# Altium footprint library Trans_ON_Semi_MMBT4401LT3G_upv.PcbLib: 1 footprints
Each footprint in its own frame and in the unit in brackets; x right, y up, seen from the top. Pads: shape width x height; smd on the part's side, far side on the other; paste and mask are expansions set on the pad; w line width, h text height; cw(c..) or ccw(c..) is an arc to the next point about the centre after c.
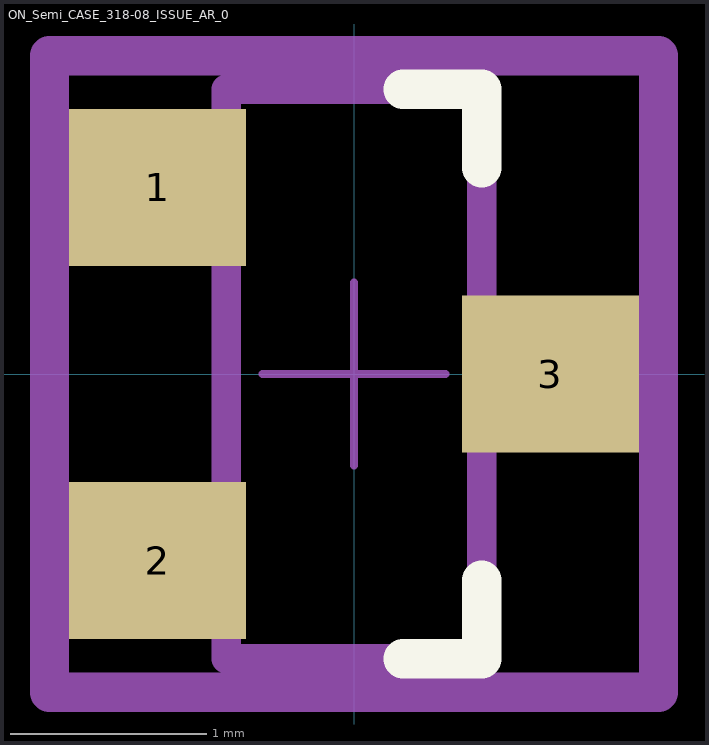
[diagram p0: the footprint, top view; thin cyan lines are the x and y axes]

## ON_Semi_CASE_318-08_ISSUE_AR_0 [mm]
pads (3):
  rect 0.9x0.8 smd: 1(-1,0.95) 2(-1,-0.95) 3(1,0)
Top Overlay:
  lines w0.2: 0.25,-1.45 0.65,-1.45 0.65,-1.05 ; 0.25,1.45 0.65,1.45 0.65,1.05
Mechanical 10:
  lines w0.2: -1.55,-1.62 1.55,-1.62 1.55,1.62 -1.55,1.62 -1.55,-1.62
  text ".Designator" at 0,0 h1
Mechanical 12:
  lines w0.15: -0.65,-1.45 -0.65,1.45 0.65,1.45 0.65,-1.45 -0.65,-1.45
Mechanical 15:
  lines w0.04: -0.465,0 0.465,0 ; 0,-0.465 0,0.465
  lines w0.1: -1.55,-1.62 -1.55,1.62 1.55,1.62 1.55,-1.62 -1.55,-1.62
3D body "Trans_MMBT4401LT3G_upv.STEP": height 1.04, standoff 0, extent -1.2,-1.45 1.2,1.45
